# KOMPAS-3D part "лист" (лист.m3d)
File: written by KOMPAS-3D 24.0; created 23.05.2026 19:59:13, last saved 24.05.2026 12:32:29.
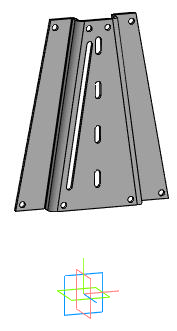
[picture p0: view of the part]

Document properties: Автор: R2D2; Полное имя файла: E:\Работа\Зайцев\GVKR1331M-1W-Fb-2P Задвижка шиберная с выдвижным штоком DN.ru Ду50-300 Ру16-10-6 с пневмоприводом\исходные материалы\DN125\лист.m3d

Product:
- Part/product: лист
    Масса: 1.314621
    Раздел спецификации: Прочие изделия
    Примечание: D040-08800

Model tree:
1. Эскиз:6  (with: Грань.Элемент выдавливания:15, Ребро.Элемент выдавливания:15)
2. Эскиз:7  (with: Грань.Элемент выдавливания:6, Ребро.Элемент выдавливания:6, Ребро.Элемент выдавливания:12)
3. Линейчатая обечайка:1
     Расстояние 1 = 10; Толщина листового тела = 4; Коэффициент = 0.5
4. Сгиб(1) - Линейчатая обечайка:1
     Радиус сгиба = 5; Коэффициент = 0.5; Величина сгиба = 5
5. Сгиб(2) - Линейчатая обечайка:1
     Радиус сгиба = 5; Коэффициент = 0.5; Величина сгиба = 5
6. Сгиб(3) - Линейчатая обечайка:1
     Радиус сгиба = 5; Коэффициент = 0.5; Величина сгиба = 5
7. Сгиб(4) - Линейчатая обечайка:1
     Радиус сгиба = 5; Коэффициент = 0.5; Величина сгиба = 5; Зазор = 1; Угол = 360; Параметр U, % = 100; Длина = 149
8. Эскиз:8  (with: Грань.Линейчатая обечайка:1, Ребро.Линейчатая обечайка:1)
9. Отверстие в листовом теле:1  (with: Грань.Линейчатая обечайка:1, Ребро.Линейчатая обечайка:1)
     Глубина выреза = 10; Диаметр отверстия = 8; Расстояние 1 = 7.5; Расстояние 2 = 7.5
10. Отверстие в листовом теле:2  (with: Грань.Линейчатая обечайка:1, Ребро.Линейчатая обечайка:1)
     Глубина выреза = 10; Диаметр отверстия = 8; Расстояние 1 = -7.5; Расстояние 2 = 7.5
11. Отверстие в листовом теле:3  (with: Грань.Линейчатая обечайка:1, Ребро.Линейчатая обечайка:1)
     Глубина выреза = 10; Диаметр отверстия = 8; Расстояние 1 = -94.6347; Расстояние 2 = 7.5
12. Отверстие в листовом теле:4  (with: Грань.Линейчатая обечайка:1, Ребро.Линейчатая обечайка:1)
     Глубина выреза = 10; Диаметр отверстия = 8; Расстояние 1 = -29.4843; Расстояние 2 = 7.5
13. Отверстие в листовом теле:5  (with: Грань.Линейчатая обечайка:1, Ребро.Линейчатая обечайка:1)
     Глубина выреза = 10; Диаметр отверстия = 8; Расстояние 1 = 7.5; Расстояние 2 = 229
14. Отверстие в листовом теле:6  (with: Грань.Линейчатая обечайка:1, Ребро.Линейчатая обечайка:1)
     Глубина выреза = 10; Диаметр отверстия = 8; Расстояние 1 = -7.5; Расстояние 2 = 229
15. Отверстие в листовом теле:7  (with: Грань.Линейчатая обечайка:1, Ребро.Линейчатая обечайка:1)
     Глубина выреза = 10; Диаметр отверстия = 8; Расстояние 1 = -31.8598; Расстояние 2 = 229
16. Отверстие в листовом теле:8  (with: Грань.Линейчатая обечайка:1, Ребро.Линейчатая обечайка:1)
     Глубина выреза = 10; Диаметр отверстия = 8; Расстояние 1 = -20.0462; Расстояние 2 = 229
17. Эскиз:9  (with: Грань.Линейчатая обечайка:1, Ребро.Линейчатая обечайка:1)
18. Эскиз:10  (with: Грань.Линейчатая обечайка:1, Ребро.Линейчатая обечайка:1)
19. Вырез в листовом теле:1
     Глубина выреза = 10
20. Вырез в листовом теле:2
     Глубина выреза = 10
21. Массив по сетке:1  (with: Вырез в листовом теле:2, Эскиз:9, Эскиз:10)  (4 pattern instances)
     Угол раствора = 90; Геометрический массив = 128

Expressions: 4*h; 2*h; v1424-70
Referenced files in E:\Работа\Зайцев\GVKR1331M-1W-Fb-2P Задвижка шиберная с выдвижным штоком DN.ru Ду50-300 Ру16-10-6 с пневмоприводом\исходные материалы\DN125\: GVKR1331E-1W-Fb-2P Задвижка шиберная с выдвижным штоком DN.ru Ду125 Ру10.a3d
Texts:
  Затвор дисковый DN.ru Ду Ру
